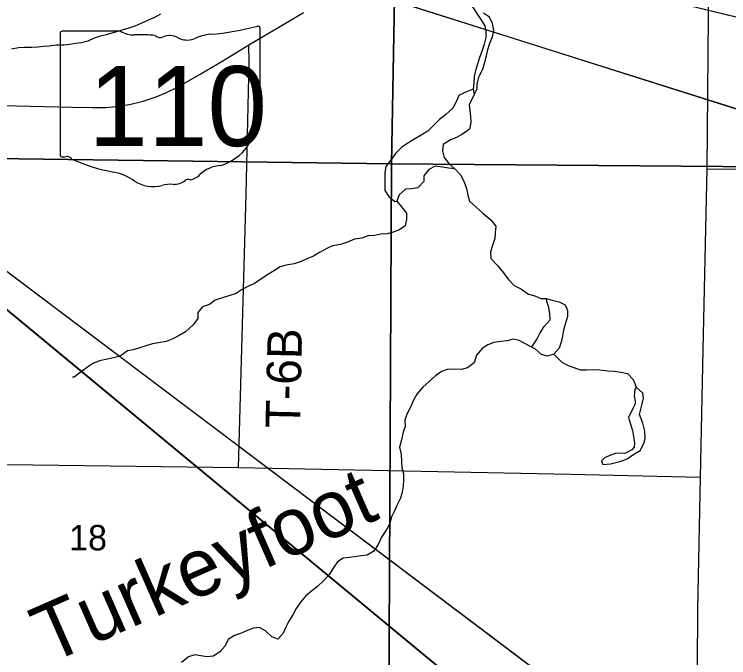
# Model space of a CAD drawing. Extents: x -6.2 to 37.4, y 0.2 to 22.2.
# Drawn here: x 7.016 to 7.605, y 18.086 to 18.616 of the extents above; entities that cross this region are included whole.
import ezdxf

# ---------------------------------------------------------------- set-up
doc = ezdxf.new("R2010")
doc.units = 0
for name, color, linetype in [('GM_X_Major_River', 7, 'Continuous'), ('GM_X_Minor_Lake', 7, 'Continuous'), ('GM_X_Minor_River', 7, 'Continuous'), ('GM_X_Minor_River_Text', 7, 'Continuous'), ('GM_X_Section', 7, 'Continuous'), ('GM_X_Section_Text', 7, 'Continuous'), ('GM_X_State_Location', 7, 'Continuous'), ('GM_X_State_Route', 7, 'Continuous'), ('GM_X_State_Shield', 7, 'Continuous'), ('GM_X_Township_Road', 7, 'Continuous'), ('GM_X_Township_Road_Text', 7, 'Continuous'), ('SH_Border', 7, 'Continuous'), ('SH_Data', 7, 'Continuous')]:
    doc.layers.add(name, color=color, linetype=linetype)

msp = doc.modelspace()

# ---------------------------------------------------------------- linework, layer by layer
at = {"layer": 'GM_X_Major_River'}
for points in [[(7.11064, 18.60462), (7.1156, 18.60625), (7.12038, 18.60845), (7.12591, 18.61083), (7.13107, 18.61302), (7.13662, 18.61616)], [(7.01366, 18.58721), (7.01936, 18.58825), (7.02429, 18.58856), (7.03036, 18.58846), (7.03529, 18.58876), (7.04005, 18.58944), (7.04476, 18.58968), (7.05049, 18.59041), (7.05675, 18.5905), (7.06169, 18.59118), (7.06644, 18.59186), (7.07138, 18.59235), (7.07671, 18.59378), (7.08187, 18.59617), (7.08695, 18.59781), (7.09178, 18.59904), (7.11064, 18.60462)]]:
    msp.add_lwpolyline(points, dxfattribs=at)
at = {"layer": 'GM_X_Minor_Lake'}
msp.add_line((7.52759, 18.29485), (7.52563, 18.29089), dxfattribs=at)
msp.add_lwpolyline([(7.52563, 18.29089), (7.52425, 18.28788), (7.5221, 18.28393), (7.52263, 18.28164), (7.52533, 18.27287), (7.52619, 18.26792), (7.52705, 18.26297), (7.52661, 18.25919), (7.52487, 18.25694), (7.51913, 18.25399), (7.51249, 18.2541), (7.50945, 18.25339), (7.50238, 18.25028), (7.49969, 18.24785), (7.50077, 18.2448), (7.50722, 18.24527), (7.51599, 18.24759), (7.52095, 18.24941), (7.52555, 18.25275), (7.53168, 18.25626), (7.53481, 18.26228), (7.53564, 18.26625), (7.53537, 18.27233), (7.53396, 18.27899), (7.53105, 18.28606), (7.53205, 18.28946), (7.53328, 18.29494), (7.5345, 18.29948), (7.53381, 18.30348), (7.5284, 18.3085), (7.52722, 18.30662), (7.52676, 18.3015), (7.52763, 18.29712), (7.52759, 18.29485)], dxfattribs=at)
at = {"layer": 'GM_X_Minor_River'}
for points in [[(7.39361, 18.62169), (7.39989, 18.6121), (7.40377, 18.60616), (7.40445, 18.6014), (7.40437, 18.59647), (7.40313, 18.59099), (7.40134, 18.58589), (7.39916, 18.58004), (7.39755, 18.57457), (7.39595, 18.56947), (7.39491, 18.56455), (7.39463, 18.55924), (7.39398, 18.55413), (7.39485, 18.54937), (7.3972, 18.55427), (7.39736, 18.55824), (7.39909, 18.56468), (7.40203, 18.57051), (7.40365, 18.57637), (7.40506, 18.58147), (7.4061, 18.58676), (7.4077, 18.59186), (7.40988, 18.59714), (7.4111, 18.60243), (7.40987, 18.60815), (7.4075, 18.61331), (7.40243, 18.61662)], [(7.39398, 18.55413), (7.38711, 18.55139), (7.38213, 18.54882), (7.37996, 18.54354), (7.3774, 18.53827), (7.37144, 18.53324), (7.36625, 18.52915), (7.36162, 18.52429), (7.35661, 18.51943), (7.35124, 18.51611), (7.34512, 18.5126), (7.34014, 18.50964), (7.33534, 18.50611), (7.33013, 18.50089), (7.32586, 18.49526), (7.32218, 18.49039), (7.32134, 18.48547), (7.32125, 18.48053), (7.32136, 18.47541), (7.32128, 18.47067), (7.3246, 18.46549), (7.32946, 18.46161), (7.33117, 18.46178)], [(7.39485, 18.54937), (7.39073, 18.54128), (7.39121, 18.53653), (7.39189, 18.53158), (7.39218, 18.52664), (7.39114, 18.52116), (7.38538, 18.51688), (7.38022, 18.51412), (7.37545, 18.5123), (7.36931, 18.50841), (7.36865, 18.50311), (7.37027, 18.49777), (7.37416, 18.49259), (7.37902, 18.48833), (7.38368, 18.48351), (7.38644, 18.47834), (7.38842, 18.47224), (7.38965, 18.46672), (7.39108, 18.46176), (7.39612, 18.45713), (7.40229, 18.45171), (7.40846, 18.44649), (7.41272, 18.44111), (7.41225, 18.4358), (7.41198, 18.43087), (7.41019, 18.42597), (7.40819, 18.41993), (7.40848, 18.41461), (7.41407, 18.40864), (7.41909, 18.40267), (7.42298, 18.39749), (7.42782, 18.39228), (7.43383, 18.38915), (7.43964, 18.38526), (7.44493, 18.38385), (7.44982, 18.38149), (7.45456, 18.38161), (7.45984, 18.38), (7.46494, 18.37897), (7.46983, 18.37643), (7.47183, 18.37165), (7.47175, 18.36672), (7.47014, 18.36124), (7.46853, 18.35557), (7.46769, 18.35065), (7.46646, 18.34555), (7.46486, 18.34064), (7.46042, 18.33578), (7.45527, 18.33396), (7.45036, 18.33537), (7.44551, 18.33981), (7.43968, 18.34275), (7.43198, 18.34686), (7.42688, 18.34808), (7.42193, 18.34665), (7.4168, 18.34616), (7.4111, 18.3453), (7.40614, 18.34348), (7.40134, 18.34034), (7.3967, 18.33491), (7.39489, 18.32867), (7.38932, 18.32459), (7.38456, 18.32315), (7.37337, 18.32333), (7.36785, 18.32152), (7.36286, 18.31799), (7.35785, 18.31333), (7.35265, 18.30867), (7.34762, 18.30287), (7.34488, 18.29779), (7.34232, 18.29214), (7.33938, 18.2863), (7.33759, 18.2814), (7.33788, 18.27627), (7.33628, 18.27136), (7.33504, 18.26512), (7.33342, 18.25907), (7.33483, 18.25317), (7.33511, 18.24709), (7.33522, 18.24216), (7.33665, 18.2372), (7.33676, 18.23245), (7.33648, 18.22714), (7.33544, 18.22204), (7.33422, 18.21712), (7.33147, 18.21166), (7.32912, 18.20677), (7.32676, 18.20168), (7.32534, 18.19639), (7.32279, 18.1915), (7.31851, 18.18493), (7.31575, 18.1789), (7.31206, 18.17346), (7.30669, 18.17013), (7.30138, 18.16964), (7.29662, 18.16877), (7.29187, 18.16828), (7.28693, 18.1676), (7.28214, 18.16464), (7.27864, 18.15957), (7.27552, 18.1545)], [(7.37902, 18.48833), (7.37372, 18.48899), (7.36881, 18.48982), (7.36275, 18.49049), (7.35759, 18.48773), (7.35352, 18.48267), (7.35344, 18.47793), (7.34842, 18.4727), (7.34348, 18.47183), (7.33817, 18.47172), (7.33315, 18.46687), (7.33117, 18.46178), (7.33488, 18.45697), (7.33897, 18.45178), (7.33907, 18.44666), (7.33803, 18.44136), (7.33285, 18.43784), (7.32808, 18.43621), (7.32332, 18.43496), (7.31782, 18.43448), (7.31268, 18.43342), (7.30756, 18.43312), (7.30241, 18.43131), (7.29633, 18.43046), (7.2906, 18.42808), (7.28469, 18.42609), (7.27822, 18.42506), (7.27345, 18.42286), (7.26751, 18.41954), (7.26234, 18.4164), (7.25699, 18.4142), (7.25222, 18.41219), (7.2465, 18.4102), (7.24003, 18.40897), (7.23508, 18.40773), (7.23029, 18.40458), (7.2255, 18.40162), (7.22071, 18.39847), (7.2138, 18.39403), (7.20845, 18.39146), (7.20367, 18.38888), (7.19869, 18.38573), (7.1882, 18.38249), (7.18153, 18.38013), (7.17673, 18.3766), (7.17101, 18.37479), (7.16713, 18.36992), (7.16705, 18.36518), (7.16336, 18.35992), (7.15701, 18.35415), (7.15184, 18.351), (7.14667, 18.34843), (7.14095, 18.34605), (7.13486, 18.34501), (7.12973, 18.34415), (7.1242, 18.34253), (7.11944, 18.3409), (7.11391, 18.33928), (7.10915, 18.33841), (7.10301, 18.33395), (7.09768, 18.33271), (7.0914, 18.33129), (7.08608, 18.33024), (7.0813, 18.32823), (7.07632, 18.32508), (7.07113, 18.32118), (7.06537, 18.31691), (7.06385, 18.31675)], [(7.44229, 18.34144), (7.44679, 18.34833), (7.44915, 18.35323), (7.45265, 18.35849), (7.45748, 18.36391), (7.45719, 18.36904), (7.45633, 18.37418), (7.45471, 18.37914), (7.45456, 18.38161)], [(7.46042, 18.33578), (7.46713, 18.32903), (7.4722, 18.32629), (7.4771, 18.32469), (7.48219, 18.32271), (7.48731, 18.32282), (7.49319, 18.32311), (7.49849, 18.32283), (7.50512, 18.32196), (7.51061, 18.32169), (7.51609, 18.32084), (7.52119, 18.31981), (7.52585, 18.31499), (7.52729, 18.31153), (7.5284, 18.3085)], [(7.27552, 18.1545), (7.27089, 18.14945), (7.26568, 18.14441), (7.26088, 18.1405), (7.25607, 18.13679), (7.25201, 18.13173), (7.24831, 18.12629), (7.24538, 18.12102), (7.24226, 18.11576), (7.23971, 18.11086), (7.23754, 18.10597), (7.23309, 18.10091), (7.22801, 18.10289), (7.22298, 18.10791), (7.2179, 18.11065), (7.21297, 18.11016), (7.20724, 18.10797), (7.20227, 18.10578), (7.19731, 18.10396), (7.19214, 18.10082), (7.18959, 18.09554), (7.18514, 18.09049), (7.18015, 18.08697), (7.17446, 18.08649), (7.16954, 18.08733), (7.16462, 18.08798), (7.15948, 18.08654), (7.15371, 18.08189)]]:
    msp.add_lwpolyline(points, dxfattribs=at)
at = {"layer": 'GM_X_Section'}
for points in [[(7.35203, 18.96803), (7.42156, 18.96788), (7.55309, 18.9944), (7.84124, 18.9938), (7.83852, 18.48836), (7.32687, 18.49251), (7.33152, 18.7501), (7.35041, 18.87769)], [(7.35203, 18.96803), (7.35041, 18.87769), (7.33152, 18.7501), (7.32687, 18.49251), (6.83509, 18.49918), (6.8456, 18.97191)], [(6.83509, 18.49918), (7.32687, 18.49251), (7.32438, 17.99011), (7.32268, 17.99032), (6.89968, 17.99325), (6.82474, 17.99671), (6.83443, 18.48586)], [(7.32687, 18.49251), (7.83852, 18.48836), (7.82976, 17.98492), (7.32438, 17.99011)]]:
    msp.add_lwpolyline(points, close=True, dxfattribs=at)
at = {"layer": 'GM_X_State_Route'}
msp.add_lwpolyline([(6.9799, 18.54093), (7.01774, 18.54031), (7.06386, 18.53917), (7.08, 18.53897), (7.09096, 18.53897), (7.10264, 18.54), (7.11195, 18.54176), (7.12219, 18.54414), (7.13294, 18.54775), (7.1407, 18.55106), (7.15104, 18.55603), (7.16893, 18.56637), (7.18775, 18.57743), (7.20916, 18.59046), (7.24607, 18.61218), (7.25434, 18.61725)], dxfattribs=at)
at = {"layer": 'GM_X_State_Shield'}
for p, q in [((7.2184, 18.55197), (7.2184, 18.60431)), ((7.05361, 18.60011), (7.05361, 18.50005)), ((7.10349, 18.60183), (7.05523, 18.60183)), ((7.21839, 18.55198), (7.2184, 18.55197))]:
    msp.add_line(p, q, dxfattribs=at)
for centre, major_axis, start_param, end_param in [((7.1597, 18.73825), (0.17476, 0), 4.814394, 5.042369), ((7.21658, 18.60453), (0.00183, 0), 6.141152, 7.989035), ((7.0555, 18.60032), (0.00191, 0), 1.712693, 3.28349), ((7.11499, 18.61345), (0.01852, 0), 4.042523, 4.731795), ((7.12113, 18.54566), (0.06648, 0), 1.404758, 1.657858), ((7.14406, 18.58928), (0.01111, 0), 0.950623, 2.079405), ((7.18199, 18.57127), (0.03516, 0), 1.699011, 2.107814), ((7.13622, 18.60084), (0.00534, 0), 3.836095, 5.185415), ((7.1584, 18.60514), (0.01336, 0), 4.081561, 5.145723), ((7.21645, 18.55177), (0.00196, 0), 5.05454, 6.418171), ((7.21798, 18.54813), (0.00284, 0), 1.883978, 3.671073), ((7.19992, 18.54151), (0.01704, 0), 5.934695, 6.695948), ((7.22498, 18.53006), (0.0124, 0), 2.387724, 3.262537), ((7.16949, 18.52341), (0.04371, 0), 5.101752, 6.440018), ((7.05552, 18.49983), (0.00193, 0), 3.00124, 4.508301), ((7.05581, 18.51007), (0.0147, 0), 4.665946, 4.897461), ((7.05882, 18.49428), (0.0053, 0), 0.519207, 1.627899), ((7.12573, 18.58418), (0.1262, 0), 4.195997, 4.488961), ((7.18792, 18.47196), (0.02394, 0), 1.647645, 2.488434), ((7.0881, 18.4551), (0.03949, 0), 0.823519, 1.323587), ((7.15759, 18.49035), (0.01412, 0), 4.937069, 5.64225), ((7.13081, 18.49378), (0.02506, 0), 4.026481, 4.996735), ((7.14529, 18.45919), (0.02059, 0), 1.495662, 1.94098), ((7.14712, 18.48629), (0.01335, 0), 4.691044, 5.507374), ((7.15919, 18.4766), (0.00376, 0), 1.147584, 2.315152)]:
    msp.add_ellipse(centre, major_axis=major_axis, ratio=0.8, start_param=start_param, end_param=end_param, dxfattribs=at)
at = {"layer": 'GM_X_Township_Road'}
for points in [[(7.57832, 17.98464), (7.57923, 18.12545), (7.5815, 18.23429), (7.58395, 18.35216), (7.58674, 18.48831), (7.58921, 18.77165), (7.59197, 18.99572)], [(7.20052, 18.24234), (7.20705, 18.4676), (7.20936, 18.57619), (7.20916, 18.59046)], [(7.58674, 18.48831), (7.8146, 18.48774), (8.03979, 18.48595), (8.33939, 18.48323)], [(6.83074, 18.24628), (7.03135, 18.24461), (7.20052, 18.24234)], [(7.20052, 18.24234), (7.29656, 18.24051), (7.47424, 18.23701), (7.5815, 18.23429)]]:
    msp.add_lwpolyline(points, dxfattribs=at)
at = {"layer": 'SH_Border'}
for p, q in [((6.58622, 18.86242), (8.99438, 18.27767)), ((8.99438, 18.09947), (6.58622, 18.86242)), ((6.58436, 18.72432), (8.99438, 16.9093)), ((8.99438, 16.73109), (6.58436, 18.72432))]:
    msp.add_line(p, q, dxfattribs=at)
at = {"layer": 'SH_Data'}
for points in [[(8.99438, 18.09947), (6.58622, 18.86242), (8.99438, 18.27767)], [(8.99438, 16.9093), (6.58436, 18.72432), (8.99438, 16.73109)]]:
    msp.add_lwpolyline(points, close=True, dxfattribs=at)

# ---------------------------------------------------------------- texts
at = {"layer": 'GM_X_Minor_River_Text'}
msp.add_text('Turkeyfoot', height=0.047378, rotation=23.74017, dxfattribs=at).set_placement((7.04417, 18.08026))
at = {"layer": 'GM_X_Section_Text'}
msp.add_text('18', height=0.020928, rotation=0.00001, dxfattribs=at).set_placement((7.06114, 18.17414))
at = {"layer": 'GM_X_State_Location'}
for s, p in [('s', (7.13416, 18.54343)), ('r', (7.13415, 18.54343))]:
    msp.add_text(s, height=0.0000947, dxfattribs=at).set_placement(p)
msp.add_text('110', height=0.0000947, rotation=0.00001, dxfattribs=at).set_placement((7.10073, 18.53654))
at = {"layer": 'GM_X_State_Shield'}
msp.add_text('110', height=0.065918, dxfattribs=at).set_placement((7.07709, 18.50711))
at = {"layer": 'GM_X_Township_Road_Text'}
msp.add_text('T-6B', height=0.028409, rotation=88.69753, dxfattribs=at).set_placement((7.25127, 18.27444))

doc.saveas('drawing.dxf')
